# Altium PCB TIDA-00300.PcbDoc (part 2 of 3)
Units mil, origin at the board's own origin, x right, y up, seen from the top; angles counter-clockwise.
Board outline 2685 x 3089 mil, 4 copper layers (Top Layer, L2_GND-PLANE, L3_PWR-PLANE, Bottom Layer), stack 63.6 mil thick; 196 components, 87 nets, 476 pads, 171 vias.
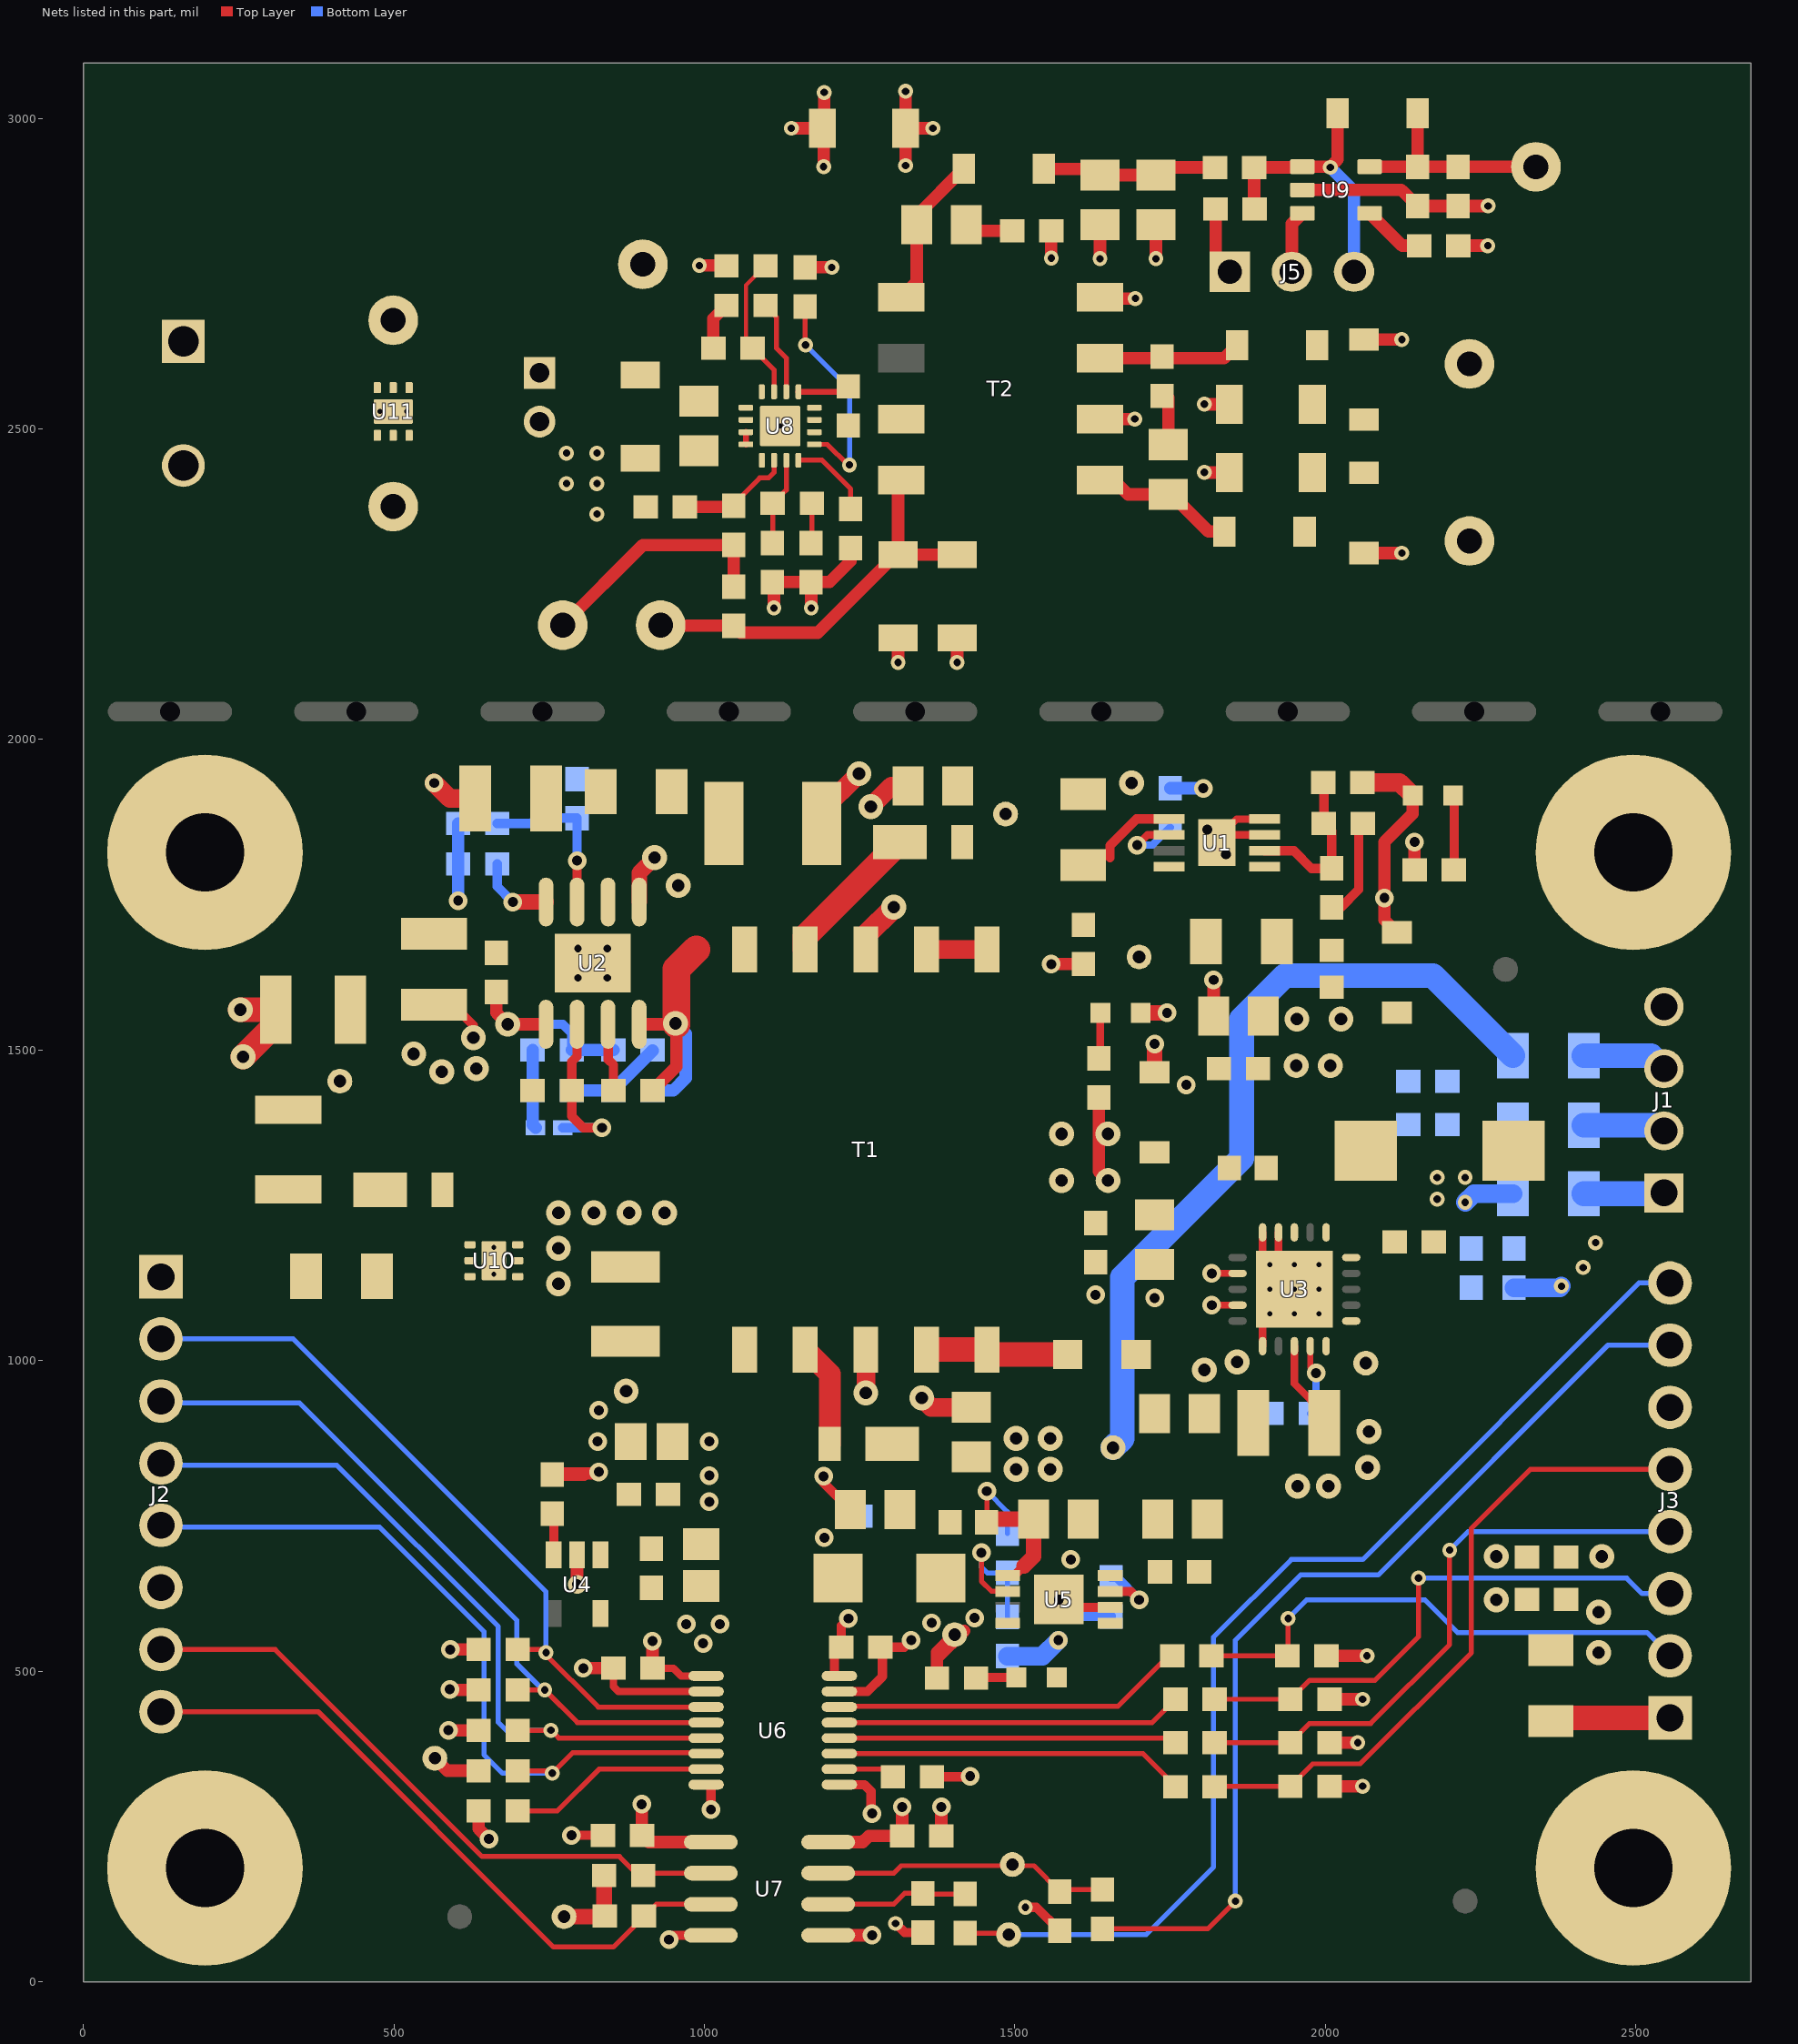
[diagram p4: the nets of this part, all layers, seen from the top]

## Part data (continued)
D1 D3 D11: "LED SmartLED Green 570NM", Alternate Manufacturer=LED, Manufacturer=OSRAM, PartNumber="LG L29K-G2J1-24-Z", Supplier Part Number 1=475-2709-2-ND
D2 D6 D9: "Diode, Schottky, 200V, 1A, PowerDI123", Manufacturer="Diodes Inc.", Supplier Part Number 1=DFLS1200DICT-ND, Value1=1A, Value2=0.85V
D4 D5: "Diode, Zener, 18V, 1W, SOD-123", Manufacturer=Panasonic, Supplier Part Number 1=DZ2W18000LCT-ND
D7: "Diode, Schottky, 60V, 1A, SOD-123F", Manufacturer="NXP Semiconductor", Supplier Part Number 1=568-4104-1-ND, Value1=1A, Value2=0.57V
D10: "DIODE ZENER 5.9V 1W PMDS", Manufacturer="Rohm Semiconductor", Supplier Part Number 1=PTZTE255.6BTR-ND, Value1=1W
D12: "Diode, Schottky, 45V, 0.1A, SOD-523", Manufacturer="Diodes Inc.", Supplier Part Number 1=SDM10U45-FDICT-ND, Value1=0.1A, Value2=0.58V
D13 D16: "Diode, Schottky, 100 V, 0.2 A, SOD-123", Manufacturer=STMicroelectronics, Supplier Part Number 1=497-5558-1-ND, Value1=0.2A, Value2=1V
D14 D15: "Diode, Zener, 16 V, 500 mW, SOD-123", Manufacturer="ON Semiconductor", Power_W=0.5, Supplier Part Number 1=MMSZ4703T1GOSCT-ND, Value1=0.5W
D17 D18: "Diode, Schottky, 30 V, 0.5 A, SOD-123", Manufacturer="Diodes Inc.", Supplier Part Number 1=B0530W-FDICT-ND, Value1=0.5A, Value2=0.43V
FID1 FID2 FID3 FID4 FID5 FID6: library part Fiducial40_0
H1 H2 H3 H4: "Machine Screw, Round, #4-40 x 1/4, Nylon, Philips panhead", Alternate Manufacturer=-, DigiKeyPartNumber=H542-ND, Manufacturer="B&F Fastener Supply"
J1: "Receptacle, 100mil, 4X1 TH", Manufacturer="TE Connectivity"
J2 J3: "Terminal Block, 8x1, 2.54 mm, TH", Manufacturer="Phoenix Contact", Supplier Part Number 1=277-1279-ND
J4: "TERMINAL BLOCK 5.08MM VERT 2POS, TH", Manufacturer="On-Shore Technology", Supplier Part Number 1=ED1609-ND
J5: "Header, 100mil, 3x1, Tin, TH", Manufacturer="TE Connectivity", Supplier Part Number 1=5-146278-3-ND
L1 L3 L4: library part MMZ1608B102C, "FERRITE CHIP 1000 OHM 300MA 0603", Manufacturer="TDK Corporation", Supplier Part Number 1=445-8672-2-ND
L2: library part IND_ELJEA_SERIES, "Inductor, Chip, ±10%", Manufacturer="EPCOS INC.", PartNumber=B82422H1332K
LBL1: library part THT-14-423-10, "Thermal Transfer Printable Labels, 0.650\" W x 0.200\" H - 10,000 per roll", Alternate Manufacturer=-, Manufacturer=Brady, Supplier Part Number 1=2065596
Logo1: library part Pb-Free
Logo2: library part FCC_disclaimer, "FCC_disclaimer"
Logo3: library part CMP-0074769-1
Logo4: library part ESD_Susceptible, "ESD Susceptible Symbol"
R1: library part CRCW04029K31FKED, "RES, 9.42k ohm, 1%, 0.063W, 0603", Manufacturer=Vishay-Dale, Power_W=0.063, Supplier Part Number 1=RNCF0603FKE9K42-ND, TempCo="100 ppm/C", Tolerance_%=1, Value1=1%, Value2=0.063W, Value_Code=9k42
R2: "RES, 110k ohm, 0.1%, 0.1W, 0603", Manufacturer="Susumu Co Ltd", Power_W=0.1, Supplier Part Number 1=RG16P110KBCT-ND, TempCo="25 ppm/C", Value1=0.1%, Value2=0.1W, Value_Code=110k
R3 R5: "RES, 4.7k ohm, 5%, 0.1W, 0603", Manufacturer=Vishay-Dale, Power_W=0.1, Supplier Part Number 1=71-CRCW0603J-4.7K-E3, TempCo="200 ppm/C", Tolerance_%=5, Value1=5%, Value2=0.1W, Value_Code=4k70
R4: "RES, 27.0k ohm, 1%, 0.1W, 0603", Manufacturer="Yageo America", Power_W=0.1, Supplier Part Number 1=311-27.0KHRCT-ND, TempCo="200 ppm/C", Tolerance_%=1, Value1=1%, Value2=0.1W, Value_Code=27k0
R6: library part RC0402JR-070RL, "RES, 0 ohm,0.1W, 1206", Manufacturer="Yageo America", Power_W=0.1, Supplier Part Number 1=311-0.0ERTR-ND, TempCo="200 ppm/C", Tolerance_%=5, Value2=0.1W, Value_Code=0000
R7 R9 R10 R11 R14 R15 R19 R20: library part RG1608P-103-B-T5, "RES, 10.0k ohm, 1%, 0.1W, 0603", Manufacturer="Vishay Dale", Power_W=0.1, Supplier Part Number 1=541-10.0KHCT-ND, TempCo="25 ppm/C", Tolerance_%=1, Value1=1%, Value2=0.1W, Value_Code=10k0
R8 R13 R16 R17 R18 R21 R25 R27 R37: library part RC0402JR-070RL, "RES, 0 ohm,5%, 0.1W, 0603", Manufacturer="Yageo America", Power_W=0.1, Supplier Part Number 1=311-0.0GRTR-ND, TempCo="200 ppm/C", Tolerance_%=5, Value1=5%, Value2=0.1W, Value_Code=0000
R12: "RES, 1.20k ohm, 0.1%, 0.1W, 0603", Manufacturer="Susumu Co Ltd", Power_W=0.1, Supplier Part Number 1=RG16P1.2KBCT-ND, TempCo="25 ppm/C", Value1=0.1%, Value2=0.1W, Value_Code=1k20
R22 R23 R24 R26: "RES, 1.50k ohm, 1%, 0.1W, 0603", Manufacturer=Vishay-Dale, Power_W=0.1, Supplier Part Number 1=541-1.50KHCT-ND, TempCo="100 ppm/C", Tolerance_%=1, Value1=1%, Value2=0.1W, Value_Code=1k50
R28: library part RT0603BRD0760K4L, "RES, 60.4k ohm, 0.1%, 0.1W, 0603", Manufacturer="Panasonic Electronic Components", Power_W=0.1, Supplier Part Number 1=P60.4KDBCT-ND, TempCo="25 ppm/C", Value1=0.1%, Value2=0.1W, Value_Code=60k4
R29: "RES, 4.87k ohm, 1%, 0.1W, 0603", Manufacturer="Yageo America", Power_W=0.1, Supplier Part Number 1=311-4.87KHRCT-ND, TempCo="200 ppm/C", Tolerance_%=1, Value1=1%, Value2=0.1W, Value_Code=4k87
R30: library part RT0603BRD07340KL, "RES, 340k ohm,1%, 0.1W, 0603", Manufacturer="Vishay Dale", Power_W=0.1, Supplier Part Number 1=541-340KHCT-ND, TempCo="25 ppm/C", Value1=1%, Value2=0.1W, Value_Code=340k
R31: library part RT0603BRD07189KL, "RES 187K OHM 1/10W .1% 0603 SMD", Manufacturer="Panasonic Electronic Components", Power_W=0.1, Supplier Part Number 1=P187KDBCT-ND, TempCo="25 ppm/C", Value1=0.1%, Value2=0.1W, Value_Code=189k
R32: library part RT0603BRD0756K2L, "RES, 56.2k ohm, 0.1%, 0.1W, 0603", Manufacturer="Panasonic Electronic Components", Power_W=0.1, Supplier Part Number 1=P56.2KDBCT-ND, TempCo="25 ppm/C", Value1=0.1%, Value2=0.1W, Value_Code=56k2
R33 R34 R35 R36: library part RC0402JR-070RL, "RES, 0 ohm,5%, 0.25W, 1206", Manufacturer="Yageo America", Power_W=0.1, Supplier Part Number 1=311-0.0ERTR-ND, TempCo="200 ppm/C", Tolerance_%=5, Value1=5%, Value2=0.125W, Value_Code=0000
R38: library part RG1608P-122-B-T5, "RES, 20K ohm, 0.1%, 0.1W, 0603", Manufacturer="Vishay Dale", Power_W=0.1, Supplier Part Number 1=TNP20.0KAACT-ND, TempCo="25 ppm/C", Value1=0.1%, Value2=0.1W, Value_Code=20K
R39: library part RG1608P-122-B-T5, "RES, 11.3K ohm, 0.1%, 0.1W, 0603", Manufacturer="panasonic electronic components", Power_W=0.1, Supplier Part Number 1=P11.3KDBCT-ND, TempCo="25 ppm/C", Value1=0.1%, Value2=0.1W, Value_Code=11K3
R40 R49: "RES, 1.0 k, 5%, 0.125 W, 0805", Manufacturer=Panasonic, Power_W=0.125, Supplier Part Number 1=P1.0KACT-ND, TempCo="200 ppm/C", Tolerance_%=5, Value1=5%, Value2=0.125W, Value_Code=1k00, ValueDisplayed=1.0k
R41 R50: "RES, 10 k, 5%, 0.1 W, 0603", Manufacturer=Vishay-Dale, Power_W=0.1, Supplier Part Number 1=541-10KGCT-ND, TempCo="200 ppm/C", Tolerance_%=5, Value1=5%, Value2=0.1W, Value_Code=10k0, ValueDisplayed=10k
R42: "RES, 220 k, 5%, 0.1 W, 0603", Manufacturer=Vishay-Dale, Power_W=0.1, Supplier Part Number 1=541-220KGCT-ND, TempCo="200 ppm/C", Tolerance_%=5, Value1=5%, Value2=0.1W, Value_Code=220k
R43: "RES, 16.2 k, 1%, 0.1 W, 0603", Manufacturer=Vishay-Dale, Power_W=0.1, Supplier Part Number 1=541-16.2KHCT-ND, TempCo="100 ppm/C", Tolerance_%=1, Value1=1%, Value2=0.1W, Value_Code=16k2, ValueDisplayed=16.2k
R44: "RES, 49.9, 1%, 0.1 W, 0603", Manufacturer=Vishay-Dale, Power_W=0.1, Supplier Part Number 1=541-49.9HCT-ND, TempCo="100 ppm/C", Tolerance_%=1, Value1=1%, Value2=0.1W, Value_Code=49R9, ValueDisplayed=49.9
R45: "RES, 75 k, 5%, 0.1 W, 0603", Manufacturer=Vishay-Dale, Power_W=0.1, Supplier Part Number 1=541-75KGCT-ND, TempCo="200 ppm/C", Tolerance_%=5, Value1=5%, Value2=0.1W, Value_Code=75k0, ValueDisplayed=75k
R46: "RES, 10.0 k, 1%, 0.1 W, 0603", Manufacturer=Vishay-Dale, Power_W=0.1, Supplier Part Number 1=541-10.0KHCT-ND, TempCo="100 ppm/C", Tolerance_%=1, Value1=1%, Value2=0.1W, Value_Code=10k0, ValueDisplayed=10.0k
R47: "RES, 0, 5%, 0.1 W, 0603", Manufacturer=Vishay-Dale, Power_W=0.1, Supplier Part Number 1=541-0.0GCT-ND, TempCo="200 ppm/C", Tolerance_%=5, Value1=5%, Value2=0.1W, Value_Code=0000, ValueDisplayed=0
R48: "RES, 240 k, 5%, 0.1 W, 0603", Manufacturer=Vishay-Dale, Power_W=0.1, Supplier Part Number 1=541-240KGCT-ND, TempCo="200 ppm/C", Tolerance_%=5, Value1=5%, Value2=0.1W, Value_Code=240k
SH-J1: "Shunt, 2.54mm, Gold, Black", Manufacturer="Wurth Elektronik", Supplier Part Number 1=732-2678-ND
T1: library part 750313995, "Transformer, 50uH, SMT", Manufacturer="Wurth Elektronik eiSos"
T2: "Transformer, 2.7 uH, SMT", Manufacturer="Wurth Elektronik", ValueDisplayed=2.7µH
TP1 TP2 TP3 TP6 TP7 TP8 TP10 TP11 TP12 TP13: library part TP-040_RND, "Test Point 40mil pad 20mil drill", Manufacturer=STD
TP4 TP5 TP9: "Test Point 40mil pad 20mil drill", Manufacturer=STD
TP14 TP15 TP17 TP20: "Test Point, Miniature, Red, TH", Color=Red, Manufacturer=Keystone, Supplier Part Number 1=36-5000-ND
TP16 TP21: "Test Point, Miniature, Black, TH", Color=Black, Manufacturer=Keystone, Supplier Part Number 1=36-5001-ND
TP18: "Test Point, Miniature, White, TH", Color=White, Manufacturer=Keystone, Supplier Part Number 1=36-5002-ND
TP19: "Test Point, Miniature, Yellow, TH", Color=Yellow, Manufacturer=Keystone, Supplier Part Number 1=36-5004-ND
U1: "-36V, -200mA, Ultralow-Noise, Negative Linear Regulator", Alternate Manufacturer=None, Manufacturer="Texas Instruments"
U2: "100V, 600mA Constant On-Time Synchronous Buck Regulator, DDA0008B", Alternate Manufacturer=None, Manufacturer="Texas Instruments"
U3: "36-V, 1-A, 4.17-µVRMS, RF LDO Voltage Regulator, RGW0020A", Alternate Manufacturer=None, Manufacturer="Texas Instruments"
U4: "IC REG LDO 3.3V 0.15A SOT23-5", Alternate Manufacturer=None, Manufacturer="Texas Instruments"
U5: library part TPS7A16XXDGN, "IC, 60-V, 6-A IQ, 100-mA, LDO Voltage Regulator with Enable and Power-Good Functions", Alternate Manufacturer=None, Manufacturer=TI
U6: library part CMP-0013040-1, "High Speed, Robust EMC Quad-Channel Digital Isolators, DBQ0016A (SSOP-16)", Alternate Manufacturer="Texas Instruments", Alternate PartNumber=ISO7741DBQ
U7: "Low-Power Bidirectional I2C Isolators, D0008A", Alternate Manufacturer=None, Manufacturer="Texas Instruments"
U8: "2.95V To 6V Input, 2W, Isolated DC/DC Converter with Integrated FETs, RTE0016F (WQFN-16)", Alternate Manufacturer="Texas Instruments"
U9: "150-mA Low-noise Low-dropout Regulator With Shutdown, DBV0005A", Alternate Manufacturer="Texas Instruments", Alternate PartNumber=LP2985-50DBVT
U10: library part CMP-0013424-7, "33-V Precision Surge Protection Clamp, DRV0006A (WSON-6)", Alternate Manufacturer="Texas Instruments", Alternate PartNumber=TVS3300DRVT
U11: library part CMP-0077837-1, "5-V Precision Surge Protection Clamp, DRV0006A (WSON-6)", Alternate Manufacturer="Texas Instruments"
ZZ1: library part AssemblyNoteLabel, Alternate Manufacturer=-
ZZ2 ZZ3 ZZ4: library part AssemblyNote, Alternate Manufacturer=-

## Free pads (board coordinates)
  oval 200x32 hole 32 slot 200 at 0 deg unplated mask+10: 0(139.44,2044.94) 0(439.44,2044.94) 0(739.44,2044.94) 0(1039.44,2044.94) 0(1339.44,2044.94) 0(1639.44,2044.94) 0(1939.44,2044.94) 0(2239.44,2044.94) 0(2539.44,2044.94)

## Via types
v1: diameter 30, hole 16, Top Layer to Bottom Layer, tented both sides, 58 vias
v2: diameter 24, hole 12, Top Layer to Bottom Layer, tented both sides, 52 vias
v3: diameter 40, hole 20, Top Layer to Bottom Layer, tented both sides, 43 vias
v4: diameter 20, hole 8, Top Layer to Bottom Layer, tented both sides, 9 vias
v5: diameter 19.68, hole 7.87, Top Layer to Bottom Layer, 5 vias
v6: diameter 25.98, hole 12, Top Layer to Bottom Layer, tented both sides, 4 vias

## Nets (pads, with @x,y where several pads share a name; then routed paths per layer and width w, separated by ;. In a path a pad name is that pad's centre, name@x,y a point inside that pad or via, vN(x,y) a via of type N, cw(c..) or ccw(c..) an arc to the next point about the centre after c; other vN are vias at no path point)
9.3V_NON_ISO: C19.1 C20.1 C26.1 C43.2 D12.2 R31.2 R37.2 T1.10 TP6.1 U4.1 | length 263.9
  Top Layer w20: R37.2@748,818.5 808,818.5 ; R37.2@755,816.5 806,816.5 808,818.5 ; v1(830,821) 827.5,818.5 808,818.5
  Bottom Layer w20: R31.2@723.5,1500 C43.2@723.5,1435 723.5,1379.84 D12.2@728.35,1375
  other v1: 828,870 830,920
+3.3V_NON_ISO: C30.1 C31.1 C35.2 C39.2 R7.2 R10.2 R11.2 R15.2 R21.1 R22.2 R23.2 TP10.1 TP12.1 U4.5 U6.1 U7.1 | length 711.4
  Top Layer w12: C35.2@916.5,505 950,505 962.5,492.5 U6.1@1010.59,492.5
  Top Layer w20: TP10.1@566,360 586,340 R15.2@636.5,340 ; v1(588,405) R10.2@636.5,405 ; v1(590,471) 591,470 R11.2@636.5,470 ; v1(591,535) R7.2@636.5,535 ; R21.1@636.5,275 636.5,246.5 v1(653,230) ; v1(899,286) 899.5,285.5 C39.2@899.5,236 910.5,225 U7.1@1010.51,225 ; C35.2@916.5,505 v1(916.5,548.5)
  Top Layer w25: TP12.1@774,105 838.5,105 R23.2@839.5,106 838.5,107 R22.2@838.5,171
  other v1: 998,545 971,576 1025,576
+5V_1: C48.1 C49.1 C50.2 J4.1 R41.2 R42.2 TP14.1 U8.1 U8.2 U8.16 U11.4 U11.5 U11.6 | length 78.2
  Top Layer w20: R42.2@1014.4,2629.67 1014.4,2677.57 R41.2@1035.5,2698.67 R41.2@1035.83,2698.34
+5V_ISO: C27.1 C36.1 C37.1 C38.2 C40.1 C45.2 D10.1 L4.2 R9.2 R12.2 R14.2 R16.2 R19.2 R20.2 R24.2 R26.2 R33.1 TP9.1 U6.16 U7.8 | length 818.2
  Top Layer w15: U6.16@1209.41,492.5 1209.41,527.91 C36.1@1220.5,539 1220.5,573.5 v1(1232,585) ; v2(1308,94) 1322.5,79.5 R24.2@1352,79.5 ; R16.2@1363.62,330 R16.2@1366.5,330 1426.98,330 v1(1427.98,331) ; v2(1517,120) 1534.5,120 R26.2@1572,82.5
  Top Layer w20: U7.8@1199.49,225 1255,225 1265,235 C40.1@1318.5,235 v1(1318.5,281.5) ; R12.2@1374.5,489 1374.5,521.5 ; TP9.1@1403,559 1374.5,530.5 1374.5,521.5 ; TP9.1@1418,565 1374.5,521.5 ; R9.2@2001.5,525 v2(2067,525) ; R20.2@2006.5,315 v2(2060,315) ; R19.2@2006.5,385 v2(2052,385) ; R14.2@2006.5,455 v2(2060,455)
  other v1: 1366,578 1435,586
  other v3: 2440,530 2440,595 2445,685
+5V_iso_1: C57.1 C58.1 D17.2 TP20.1 U9.5 | length 354.1
  Top Layer w20: U9.5@2071.13,2922.07 2148.14,2922.07 C58.1@2148.33,2921.88 ; D17.2@2148.47,3008 2148.33,3007.86 C58.1@2148.33,2921.88 ; TP20.1@2339,2921.88 C57.1@2213.33,2921.88 C58.1@2148.33,2921.88
+6V_ISO: C22.1 C29.1 C32.2 D7.1 R36.1 TP8.1 U5.5 U5.8 | length 1295.1
  Bottom Layer w40: TP8.1@1658,860 1673,875 1673,1134 1865,1326 1865,1550 1935,1620 2172.91,1620 R36.1@2301.91,1491
+15V_ISO: C17.2 C18.1 C33.2 C34.2 D5.1 L3.2 R5.1 R34.1 TP5.1 | length 222.4
  Top Layer w20: R5.1@1635,1423.5 1635,1305 TP5.1@1650,1290
  Bottom Layer w30: v2(2225,1255) 2239,1269 R34.1@2301.91,1269
  other v2: 2180,1260 2180,1295 2225,1295
  other v3: 1575,1290 1575,1365 1650,1365
+15V_iso_1: C51.1 D13.1 D14.1 TP15.1
+18V_ISO: C21.1 C23.1 D9.1 TP7.1 U3.13 U3.15 U3.16 | length 137.4
  Top Layer w12: U3.13@1950,1023.46 1950,963 1998,915 C23.1@2007.09,915
  other v3: 1955,798 2005,798 1502,825 1557,825 2068,828 1502,875 1557,875 2070,886
+24VDC_LIMIT: J2.1 R6.2
-15V_ISO: C10.2 C12.2 C24.1 C25.2 D4.2 L1.2 R3.1 R35.1 TP4.1 | length 46
  Top Layer w20: R3.1@2143.5,1790 v1(2143.5,1835)
  Top Layer w30: D4.2@2115,1560.53 D4.2@2115.96,1560.53
  other v3: 2008,1475 1954,1550 2025,1550
-15V_iso_1: C54.2 D15.2 D16.2 TP17.1
-18V_ISO: C1.2 C5.1 C7.2 D2.2 TP1.1 U1.5 U1.8 | length 132.3
  Top Layer w15: 1653,1810 1653,1829.13 1695.87,1872 U1.5@1748.4,1872
/CS0: J2.2 R7.1 U6.3 | length 1239.2
  Top Layer w8: R7.1@699.5,535 736.82,535 v2@741.82,530 ; v2(745,530) v2@741.82,530 ; U6.3@1010.59,442.5 829.32,442.5 v2@741.82,530
  Bottom Layer w8: J2.2@125,1035 338.08,1035 745,628.08 v2(745,530)
/CS0_ISO: J3.2 R8.2 R9.1 | length 847.3
  Top Layer w8: R8.2@1816.5,525 R9.1@1938.5,525 1940,526.5 v2(1940,585)
  Bottom Layer w8: v2(1940,585) 1970,615 2160,615 2212.5,562.5 2517.5,562.5 J3.2@2555,525
DGND_1: C47.2 C48.2 C49.2 C50.1 C55.2 C56.2 C59.2 C64.1 J4.2 R45.1 R46.1 R48.1 R50.1 TP16.1 TP21.1 U8.3 U8.4 U8.5 U8.17@1122,2504.67 U11.1 U11.2 U11.3 U11.7@499,2528 | length 607.2
  Top Layer w6: C64.1@1106.72,2251.05 1111.72,2256.05 C64.1@1113.1,2254.67
  Top Layer w10: U8.4@1066.88,2475.14 U8.3@1066.88,2494.83
  Top Layer w20: v2(992,2763) 1035.17,2763 R45.1@1035.5,2762.67 ; v2(1112,2211.67) C64.1@1112,2253.17 ; C64.1@1114.24,2253.53 1201.65,2253.53 1235.54,2287.43 R48.1@1235.54,2307.98 ; v2(1140,2984) 1189.74,2984 C47.2@1190.07,2983.67 C47.2@1190.4,2983.34 ; C59.2@1161.67,2760.5 C59.2@1162,2760.17 v2(1205.17,2760.17) ; v2(1172,2211.67) R50.1@1172,2253.17 ; C47.2@1190.73,2983.67 C47.2@1190.4,2983.34 ; v2(1192,2922) 1192,2981.74 C47.2@1190.4,2983.34 ; C47.2@1193,2982 v2(1193,3041.74) ; v2(1312,2124) C55.2@1312,2163.74 ; v2(1407,2124) C56.2@1407,2163.74
  other v2: 827,2363 778,2412 827,2412 778,2461 827,2461
  other v5: 1122,2504.67 477.35,2528 520.65,2528
GND: C2.1 C3.1 C4.2 C9.2 C11.1 C13.2 C19.2 C20.2 C26.2 C30.2 C31.2 C35.1 C39.1 H1.1 H3.1 J2.6 R4.1 R29.1 U2.1 U2.9 U4.2 U6.2 U6.8 U7.4 U10.1 U10.2 U10.3 U10.7@661,1161 | length 856.6
  Top Layer w12: C35.1@853.5,505 853.5,475.3 861.3,467.5 U6.2@1010.59,467.5
  Top Layer w15: C9.2@565,1572.91 595.09,1572.91 628,1540 v3(628,1520) ; v1(786,236) C39.1@836.5,236 ; v1(943,68) 950,75 U7.4@1010.51,75 ; v1(1010.59,277.41) U6.8@1010.59,317.5
  Top Layer w20: v1(795,640) U4.2@795,687.24 ; v1(805,505) C35.1@853.5,505
  Top Layer w25: U2.1@895,1738.43 895,1785 v3(920,1810)
  Top Layer w30: v1(565,1930) 590,1905 C2.1@630.91,1905
  Top Layer w40: v3(253,1565) C11.1@310,1565 310,1542 v3(257,1489)
  other v1: 1008,773 1008,815 1008,870
  other v3: 765,1124 765,1181 765,1238 822,1238 879,1238 936,1238 577,1465 633,1470 532,1494 958,1765
  other v5: 661,1139.35 661,1182.65
  other v6: 796.38,1616.38 843.62,1616.38 796.38,1663.62 843.62,1663.62
GND_ISO: C1.1 C4.1 C5.2 C7.1 C8.2 C10.1 C12.1 C15.1 C16.2 C17.1 C18.2 C21.2 C22.2 C23.2 C24.2 C25.1 C27.2 C28.2 C29.2 C32.1 C33.1 C34.1 C36.2 C37.2 C38.1 C40.2 C41.2 C44.2 C45.1 C46.2 D1.2 D3.1 D4.1 D5.2 D10.2 D11.1 H2.1 H4.1 J1.4 J3.6 R1.2 R39.1 T1.3 T1.8 TP2.1 U1.3 U1.4 U1.9 U3.4 U3.5 U3.7 U3.9 U3.11 U3.21 U5.4 U5.6 U5.9 U6.9 U6.15 U7.5 | length 2272.1
  Top Layer w11: v1(1817,1089.41) U3.9@1858.46,1089.41 ; v1(1817,1140.59) U3.7@1858.46,1140.59
  Top Layer w12: U1.9@1825,1834 U1.9@1837.4,1846.4 ; U3.11@1898.82,1023.46 U3.21@1898.82,1083.23 ; U3.21@1898.82,1166.18 U3.5@1898.82,1206.54 ; U1.3@1902,1846.4 U1.9@1837.4,1846.4 ; U1.4@1902,1872 1857,1872 1831.4,1846.4 U1.9@1837.4,1846.4 ; U3.21@1910.63,1140.59 1924.41,1140.59 U3.4@1924.41,1206.54
  Top Layer w15: v1(1192,814) 1192,803 C27.2@1235,760 ; U6.9@1209.41,317.5 1257.5,317.5 1268.32,306.68 1268.32,272.68 v1(1270,271) ; U6.15@1209.41,467.5 1262.5,467.5 1286.5,491.5 C36.2@1286.5,539 ; C36.2@1283.5,539 C36.2@1286.5,539 ; v1(1332.99,550) 1321.99,539 C36.2@1286.5,539 ; v1(1570.8,615.6) 1583.5,602.9 U5.6@1653.5,602.9
  Top Layer w20: U7.5@1199.49,75 v1(1270,75) ; C40.2@1381.5,235 v1(1381.5,281.5) ; v1(1558.5,1638.5) C7.1@1610,1638.5 ; C10.1@1820,1555 v1(1820,1613) ; D4.1@2115,1689.47 2095,1709.47 v1(2095,1745) 2095,1835 2140.52,1880.52 D1.2@2140.52,1910
  Top Layer w25: D3.1@1702.48,1560 v1(1745,1560) ; D5.2@1725,1464.47 v1(1725,1510)
  Top Layer w30: C4.1@1188.74,1865 1188.74,1884.74 v3(1249,1945) ; v3(1260,948) T1.8@1260,1017.95 ; v3(1268,1892) 1301,1925 C1.1@1328,1925 ; v3(1350,940) 1365,925 C21.2@1430,925 ; R1.2@2059.5,1931 2119.52,1931 D1.2@2140.52,1910
  Top Layer w35: T1.3@1260,1662.05 1260,1685 v3(1305,1730)
  Bottom Layer w15: v1(1570.8,615.6) 1597.9,588.5 C46.2@1655,588.5
  Bottom Layer w20: C41.2@1750,1921.5 v1(1803.5,1921.5)
  Bottom Layer w30: R39.1@1488,524.5 1544.5,524.5 v1(1570,550) ; C34.1@2304,1117.5 2377.5,1117.5 v2(2380,1120)
  other v1: 1590,680 1193,715 1725,1101 1630,1106 1776,1444 1840,1815 1810,1855
  other v2: 2415,1150 2435,1190
  other v3: 2275,615 2275,685 1805,985 1858,998 1688,1930
  other v4: 1910.63,1075.63 1950,1075.63 1989.37,1075.63 1910.63,1115 1950,1115 1989.37,1115 1910.63,1154.37 1950,1154.37 1989.37,1154.37
GND_iso_1: C47.1 C51.2 C54.1 C57.2 C58.2 C60.2 C61.1 C63.2 C65.2 C66.2 D14.2 D15.1 J5.1 T2.5 T2.7 U9.2 | length 1083.7
  Top Layer w20: v2(1323.93,2923.93) C47.1@1323.93,2983.67 ; v2(1323.93,3043.41) C47.1@1323.93,2983.67 ; v2(1368,2984) 1324.26,2984 C47.1@1323.93,2983.67 ; C65.2@1558.49,2818.67 1558.49,2775.12 v2(1558.61,2775) ; v2(1637,2774.04) C60.2@1637,2828.67 ; T2.7@1637.04,2515.65 v2@1693,2515.65 ; T2.5@1649.08,2709.67 v2@1693.98,2709.67 ; v2(1727,2774.04) C61.1@1727,2828.67 ; v2@1805,2429.67 C51.2@1843.12,2429.67 ; v2@1805,2539.67 C54.1@1843.12,2539.67 ; C63.2@1823.2,2854.14 1823.2,2775.8 J5.1@1846,2753 ; U9.2@1962.87,2884.67 2121.7,2884.67 2121.7,2884.2 2123.02,2884.2 C58.2@2148.33,2858.89 C57.2@2213.33,2858.89 v2(2261.89,2858.89) ; D14.2@2062,2300.2 v2@2122.86,2300.2 ; D15.1@2062,2644.14 2122.86,2644.14 v2(2123,2644) ; C66.2@2214,2795 v2(2261.47,2795)
  other v2: 2123,2300.06 1805,2430 1693,2516 1805,2540 1693.98,2710.02
MISO: J2.5 R15.1 U6.6 | length 1233
  Top Layer w8: R15.1@699.5,340 759,340 787.81,368.81 U6.6@1009.28,368.81
  Bottom Layer w8: J2.5@125,735 128,732 477.05,732 645,564.05 645,366 675,336 v2(755,336)
MISO_ISO: J3.5 R18.2 R20.1 | length 1061.9
  Top Layer w8: R18.2@1821.5,315 R20.1@1943.5,315 1979.5,351 2056,351 2235,530 2235,730 2330,825 J3.5@2555,825
MOSI: J2.4 R10.1 U6.5 | length 1212.6
  Top Layer w8: R10.1@699.5,405 v2(753,405) 765.5,392.5 U6.5@1010.59,392.5
  Bottom Layer w8: J2.4@125,835 128,832 408,832 668,572 668,418 681,405 v2(753,405)
MOSI_ISO: J3.4 R17.2 R19.1 | length 963.4
  Top Layer w8: R17.2@1821.5,385 R19.1@1943.5,385 1974.5,416 2073,416 2200,543 v2(2200,695)
  Bottom Layer w8: v2(2200,695) 2230,725 J3.4@2555,725
NetC2_2: C2.2 C3.2 C9.1 C11.2 L2.2 R28.2 R30.2 TP3.1 U2.2 | length 124.5
  Bottom Layer w20: v1(603.5,1740.5) R30.2@603.5,1800 R28.2@603.5,1865
NetC6_1: C6.1 C8.1 L1.1 R2.2 U1.1 | length 169.9
  Top Layer w15: C6.1@2005,1729.5 C6.1@2010,1729.5 2024.5,1729.5 2053.62,1758.62 2053.62,1858.13 R2.2@2060.5,1865
NetC6_2: C6.2 R1.1 R2.1 U1.2 | length 263.8
  Top Layer w15: U1.2@1902,1820.8 1949.2,1820.8 1977.5,1792.5 C6.2@2010,1792.5 2010,1852.5 R2.1@1997.5,1865 1997.5,1930 R1.1@1996.5,1931
NetC13_1: C13.1 D12.1 U2.6 | length 271.1
  Top Layer w15: U2.6@795,1541.57 795,1490 786.5,1481.5 C13.1@786.5,1435 786.5,1393.5 805,1375 v1(835,1375)
  Bottom Layer w15: D12.1@771.65,1375 v1(835,1375)
NetC14_1: C14.1 U2.7 | length 110.1
  Top Layer w15: U2.7@845,1541.57 845,1485 853.5,1476.5 C14.1@853.5,1435
NetC14_2: C14.2 R32.2 T1.1 U2.8 | length 472.9
  Top Layer w20: U2.8@895,1541.57 955,1541.57 955,1473.5 C14.2@916.5,1435
  Top Layer w45: v3@955,1541.57 955,1630 987.05,1662.05
  Bottom Layer w20: R32.2@916.5,1435 950,1435 970,1455 970,1526.43 v3(953.43,1543)
NetC15_2: C15.2 C16.1 L3.1 U3.1 U3.3 U3.20
NetC28_1: C28.1 L4.1 R38.2 U5.1 | length 323.5
  Top Layer w8: L4.1@1454.53,740 1455,740.47 v1(1455,790)
  Top Layer w15: U5.1@1488.5,654.2 1499.2,654.2 1514.6,669.6
  Top Layer w25: L4.1@1455,740.47 1459.53,745 C28.1@1530,745 1530,685 1514.6,669.6
  Bottom Layer w8: v1(1455,790) 1488,757 R38.2@1488,721.5
NetC41_1: C41.1 U1.6 | length 123
  Top Layer w12: v1(1697,1830) 1713.4,1846.4 U1.6@1748.4,1846.4
  Bottom Layer w12: v1(1697,1830) 1721.5,1830 C41.1@1750,1858.5
NetC42_1: C42.1 C43.1 R32.1 | length 156.1
  Bottom Layer w20: C43.1@786.5,1435 R32.1@853.5,1435 ; R32.1@853.5,1436.16 C42.1@916.5,1499.15
NetC42_2: C42.2 R4.2 R31.1 U2.5 | length 324.4
  Top Layer w20: R4.2@665,1593.5 665,1560 v3(683.43,1541.57) ; v3(683.43,1541.57) U2.5@745,1541.57
  Bottom Layer w15: v3(683.43,1541.57) 772.19,1541.57 786.5,1527.27 R31.1@786.5,1500
  Bottom Layer w20: R31.1@786.5,1500 C42.2@853.5,1500
NetC44_1: C44.1 U3.14 | length 115.9
  Top Layer w10: U3.14@1975.59,1023.46 1975.59,989.41 v1(1985,980)
  Bottom Layer w12: C44.1@1976.5,915 1985,923.5 v1(1985,980)
NetC46_1: C46.1 U5.7 | length 112.2
  Top Layer w15: U5.7@1653.5,628.5 1686.5,628.5 v1(1700,615)
  Bottom Layer w15: C46.1@1655,651.5 1663.5,651.5 v1(1700,615)
NetC52_1: C52.1 T2.2 U8.10 U8.11 U8.12
NetC52_2: C52.2 U8.13 | length 84.1
  Top Layer w10: U8.13@1151.52,2559.79 1223.29,2559.79 C52.2@1232,2568.5
NetC53_1: C53.1 R40.1 | length 72.6
  Top Layer w20: R40.1@1747,2477.66 C53.1@1747,2550.24
NetC53_2: C53.2 D16.1 T2.6 | length 229.2
  Top Layer w20: T2.6@1637.04,2613.69 1836.54,2613.69 D16.1@1857.53,2634.67
NetC55_1: C55.1 C56.1 R44.2 T2.1 TP19.1 | length 656.5
  Top Layer w20: TP19.1@929.61,2184 930.44,2183.17 R44.2@1047,2183.17 1058.17,2172 1182.63,2172 1308.23,2297.6 C55.1@1312,2297.6 ; T2.1@1316.96,2417.62 1312,2412.66 C55.1@1312,2297.6 ; C56.1@1407,2297.6 C55.1@1312,2297.6
NetC59_1: C59.1 U8.9 | length 367.6
  Top Layer w8: v2(1163,2635) 1163,2642.57 1162,2643.57 C59.1@1162,2697.17 C59.1@1170.9,2688.27 ; U8.9@1177.11,2475.14 1197.94,2475.14 1231.09,2442 v2(1233.61,2442)
  Bottom Layer w8: v2(1163,2635) 1233.61,2564.39 v2(1233.61,2442)
NetC60_1: C60.1 C61.2 D18.1 R47.1 | length 287.2
  Top Layer w20: D18.1@1544.36,2918.67 1627,2918.67 C60.1@1637,2908.67 C61.2@1727,2908.67 1739.33,2921 R47.1@1822.26,2921
NetC62_1: C62.1 C64.2 U8.7 | length 142.3
  Top Layer w8: C64.2@1109.61,2316.5 1110.11,2317 C62.1@1110.11,2380 1131.84,2401.73 U8.7@1131.84,2449.55
NetC62_2: C62.2 R50.2 | length 66.4
  Top Layer w6: R50.2@1174.24,2316.52 R50.2@1175.74,2318.02
  Top Layer w8: R50.2@1172,2316.17 1173.11,2317.27 C62.2@1173.11,2380
NetC63_1: C63.1 D17.1 J5.3 R47.2 U9.1 | length 464.9
  Top Layer w20: C63.1@1886.19,2854.14 1885.25,2855.07 R47.2@1885.25,2921 1961.8,2921 U9.1@1962.87,2922.07 2008,2922.07 2019.53,2933.6 D17.1@2019.53,3008
  Bottom Layer w20: v2(2008,2921) 2046,2883 J5.3@2046,2753
NetC65_1: C65.1 R49.1 | length 77.6
  Top Layer w20: R49.1@1422,2828.67 1432,2818.67 C65.1@1495.5,2818.67
NetC66_1: C66.1 U9.4 | length 101.5
  Top Layer w20: U9.4@2071.13,2847.27 2123.4,2795 C66.1@2151.01,2795
NetD1_1: D1.1 R3.2 | length 119
  Top Layer w15: R3.2@2207.48,1790.98 D1.1@2207.48,1910
NetD2_1: D2.1 T1.2 | length 214.9
  Top Layer w40: T1.2@1162.36,1662.05 1162.36,1682.56 D2.1@1299.8,1820
NetD3_2: D3.2 R5.2 | length 74.5
  Top Layer w12: R5.2@1635,1486.5 1637.52,1489.02 D3.2@1637.52,1560
NetD6_1: D6.1 L2.1
NetD6_2: D6.2 R6.1 U10.4 U10.5 U10.6
NetD7_2: D7.2 T1.6 T1.7 | length 230.5
  Top Layer w40: T1.7@1357.64,1017.95 T1.6@1455.28,1017.95 1463.23,1010 D7.2@1584.88,1010
NetD9_2: D9.2 T1.9 | length 168.3
  Top Layer w35: T1.9@1162.36,1017.95 1201.8,978.51 1201.8,941 D9.2@1201.8,866
NetD11_2: D11.2 R12.1 | length 65.4
  Top Layer w15: R12.1@1437.5,489 1438.5,490 D11.2@1502.52,490
NetD13_2: D13.2 R40.2 T2.8 | length 234.9
  Top Layer w20: T2.8@1637.04,2417.62 1659.04,2417.62 1682,2394.67 R40.2@1747,2394.67 1752,2394.67 1812,2334.67 D13.2@1837.53,2334.67
NetD18_2: D18.2 R49.2 T2.4 | length 248.6
  Top Layer w20: T2.4@1316.96,2711.72 1342,2736.76 R49.2@1342,2828.67 1342,2843.14 D18.2@1417.53,2918.67
NetJ1_1: J1.1 R34.2 | length 148.4
  Top Layer w30: J1.1@2531.5,1283.5 J1.1@2545,1270
  Bottom Layer w40: R34.2@2416.09,1269 2544,1269 J1.1@2545,1270
NetJ1_2: J1.2 R35.2 | length 132.6
  Bottom Layer w40: R35.2@2416.09,1379 2536,1379 J1.2@2545,1370
NetJ1_3: J1.3 R36.2 | length 137.6
  Bottom Layer w40: R36.2@2416.09,1491 2524,1491 J1.3@2545,1470
NetJ3_1: J3.1 R33.2 | length 194.1
  Top Layer w40: R33.2@2363,419.91 2368.09,425 J3.1@2555,425
NetJ5_2: J5.2 U9.3 | length 101.3
  Top Layer w20: J5.2@1946,2753 1946,2830.4 U9.3@1962.87,2847.27
NetR8_1: R8.1 U6.14 | length 578.3
  Top Layer w8: U6.14@1209.41,442.5 1210.72,443.81 1666.18,443.81 1747.37,525 R8.1@1753.5,525
NetR13_1: R13.1 U6.13 | length 564.6
  Top Layer w8: U6.13@1209.41,417.5 1721,417.5 R13.1@1758.5,455
NetR16_1: R16.1 U6.10 | length 99.3
  Top Layer w8: U6.10@1209.41,342.5 1291,342.5 R16.1@1303.5,330
NetR17_1: R17.1 U6.12 | length 555.7
  Top Layer w8: U6.12@1211.91,395 1209.41,392.5 1751,392.5 R17.1@1758.5,385
NetR18_1: R18.1 U6.11 | length 570.8
  Top Layer w8: U6.11@1209.41,367.5 1706,367.5 R18.1@1758.5,315
NetR21_2: R21.2 U6.7 | length 339.1
  Top Layer w8: R21.2@699.5,275 763,275 830.5,342.5 U6.7@1010.59,342.5
NetR24_1: R24.1 R25.1 U7.6 | length 228.2
  Top Layer w8: U7.6@1199.49,125 1304.8,125 1322.3,142.5 R24.1@1352,142.5 1353,141.5 R25.1@1420,141.5
NetR26_1: R26.1 R27.1 TP11.1 U7.7 | length 464.9
  Top Layer w8: U7.7@1199.49,175 1305,175 1317,187 1530.5,187 R26.1@1572,145.5 1575,148.5 R27.1@1641,148.5
NetR28_1: R28.1 R29.2 U2.3 | length 267.1
  Top Layer w15: U2.3@795,1738.43 v1(795,1805)
  Bottom Layer w15: R28.1@666.5,1865 721.5,1865 730,1873.5 R29.2@795,1873.5 v1(795,1805)
NetR30_1: R30.1 U2.4 | length 125.4
  Top Layer w25: v1(691.57,1738.43) U2.4@745,1738.43
  Bottom Layer w15: R30.1@666.5,1800 666.5,1763.5 v1(691.57,1738.43)
NetR37_1: R37.1 U4.3 | length 72.2
  Top Layer w15: R37.1@748,755.5 757.6,745.91 U4.3@757.6,687.24
NetR38_1: R38.1 R39.2 U5.2 | length 235.2
  Top Layer w8: v1(1446,691) 1446,645 1462.4,628.6 U5.2@1488.5,628.6
  Bottom Layer w8: v1(1446,691) 1446,668 1455.5,658.5 R38.1@1488,658.5 R39.2@1488,587.5
NetR41_1: R41.1 U8.14 | length 153.1
  Top Layer w8: R41.1@1097.39,2698.67 1115.9,2680.17 1115.9,2630.1 1131.84,2614.16 U8.14@1131.84,2559.79
NetR42_1: R42.1 R45.2 U8.15 | length 234.6
  Top Layer w6: R42.1@1077.39,2629.67 1067,2640.07 1067,2731.17 R45.2@1098.49,2762.67
  Top Layer w8: R42.1@1077.39,2629.67 1112.15,2594.91 U8.15@1112.15,2559.79
NetR43_1: R43.1 R44.1 TP18.1 | length 395.5
  Top Layer w20: TP18.1@772,2184 901.17,2313.17 R43.1@1047,2313.17 R44.1@1047,2246.17
NetR43_2: R43.2 R46.2 U8.6 | length 171.2
  Top Layer w8: R43.2@1045.9,2377.66 1089.24,2421 1103.33,2421 1112.15,2429.83 U8.6@1112.15,2449.55
  Top Layer w20: R46.2@983.49,2374.67 1042.91,2374.67 R43.2@1045.9,2377.66
NetR48_2: R48.2 U8.8 | length 135.5
  Top Layer w8: U8.8@1151.52,2449.55 1189.32,2449.55 1235.54,2403.33 R48.2@1235.54,2370.97
NetT1_4: T1.4 T1.5 | length 97.6
  Top Layer w30: T1.4@1357.64,1662.05 T1.5@1455.28,1662.05
SCL: J2.8 R23.1 U7.3 | length 1071.1
  Top Layer w8: J2.8@125,435 378,435 757,56 853.5,56 922.5,125 U7.3@1010.51,125
SCL_ISO: J3.8 R25.2 TP13.1 | length 1787.3
  Top Layer w8: R25.2@1420,78.5 1487.5,78.5 TP13.1@1490,76
  Bottom Layer w8: TP13.1@1490,76 1711,76 1820,185 1820,555 1945,680 2060,680 2505,1125 J3.8@2555,1125
SCLK: J2.3 R11.1 U6.4 | length 1184.6
  Top Layer w8: R11.1@699.5,470 v2(743,470) 795.5,417.5 U6.4@1010.59,417.5
  Bottom Layer w8: J2.3@125,935 128,932 348,932 698,582 698,511.73 739.73,470 v2(743,470)
SCLK_ISO: J3.3 R13.2 R14.1 | length 879.9
  Top Layer w8: R13.2@1821.5,455 R14.1@1943.5,455 1944.11,455 1974.81,485.7 2080,485.7 2150,555.7 v2(2150,650)
  Bottom Layer w8: v2(2150,650) 2485,650 2510,625 J3.3@2555,625
SDA: J2.7 R22.1 U7.2 | length 1043.5
  Top Layer w8: J2.7@125,535 309,535 642.3,201.7 863.16,201.7 893.86,171 R22.1@901.5,171 ; R22.1@899.63,162 912.63,175 U7.2@1010.51,175
SDA_ISO: J3.7 R27.2 | length 1549.2
  Top Layer w8: R27.2@1641,85.5 1810.5,85.5 v2(1855,130)
  Bottom Layer w8: v2(1855,130) 1855,550 1960,655 2085,655 2455,1025 J3.7@2555,1025
pads on no net: FID1.1 FID2.1 FID3.1 FID4.1 FID5.1 FID6.1 SH-J1.0 T2.3 U1.7 U3.2 U3.6 U3.8 U3.10 U3.12 U3.17 U3.18 U3.19 U4.4 U5.3 U8.17@1122,2504.67 U10.7@661,1143.28 U10.7@661,1178.72 U11.7@481.28,2528 U11.7@516.72,2528

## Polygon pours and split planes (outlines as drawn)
NetD6_2 on Top Layer "vdd" (solid, remove dead copper, pour order 153): 561,1158 553,1150 515,1150 512,1153 512,1175.25 505.25,1182 446,1182 440,1176 440,1097 446,1091 627,1091 633,1097 633,1306 626,1313 565,1313 561,1309
+5V_iso_1 on Top Layer "vdd" (solid, remove dead copper, pour order 125): 2109,2943 2119,2953 2119,3027 2130,3038 2196,3038 2203,3031 2203,2989 2211,2981 2391.48,2981 2399.48,2973 2399.48,2875.48 2392,2868 2311,2868 2282,2897 2057,2897 2049,2905 2049,2938 2054,2943
DGND_1 on Top Layer "vdd" (solid, remove dead copper, pour order 123): 130,2539 110,2519 110,2314 123.8,2300.2 786.53,2300.2 825.33,2339 923,2339 931,2347 931,2414 939,2422 1087.91,2422 1098.49,2432.58 1098.49,2460.81 1106.72,2469.04 1153.04,2469.04 1157,2473 1157,2534 1152,2539 1090,2539 1088,2537 1088,2499 1034,2499 1028,2493 815.02,2493 769.02,2539
NetC52_1 on Top Layer "NETC52_1_L01_P117" (solid, remove dead copper, pour order 117): 1165.88,2539.67 1192,2539.67 1197,2534.67 1352,2534.67 1352,2484 1165.73,2484
-15V_iso_1 on Top Layer "-15V_ISO_1_L01_P115" (solid, pour order 115): 2152,2494.67 2263.67,2494.67 2276,2507 2276,2640 2264,2652 2197,2652 2185,2640 2185,2580.5 2159.17,2554.67 2007,2554.67 2007,2665.61 1997.94,2674.67 1959.28,2674.67 1952,2667.39 1952,2502.61 1959.94,2494.67
+15V_iso_1 on Top Layer "+15V_ISO_1_L01_P113" (solid, pour order 113): 2265.56,2454.67 2276.23,2444 2276.23,2289.34 2261.89,2275 2201,2275 2188,2288 2188,2354.98 2173.31,2369.67 1987,2369.67 1987,2309.67 1982,2304.67 1945.94,2304.67 1942,2308.61 1942,2359.67 1942,2459.58 1947.09,2464.67 2001.61,2464.67 2011.61,2454.67
+5V_1 on Top Layer "+5V_1_L01_P107" (solid, pour order 107): 119,2562 105,2576 105,2715 129,2739 821.57,2739 894.57,2666 1031.9,2666 1045.9,2652 1045.9,2589.67 1050.9,2584.67 1080.9,2584.67 1095.9,2569.67 1095.9,2549.67 1080.9,2549.67 1075.9,2544.67 1075.9,2514.67 1070.9,2509.67 1050.9,2509.67 1040.9,2519.67 868.33,2519.67 827,2561 738,2561 737,2562
GND_ISO on Top Layer "Top Layer-No Net 1" (hatched 90Degree grid 5 track 10, remove dead copper, pour order 68): 1190,630 1185,635 1185,760 1202,790 1259,790 1259,724 1244,724 1240,720 1240,635 1235,630
+18V_ISO on Top Layer "Top Layer-No Net 1" (hatched 90Degree grid 5 track 10, remove dead copper, pour order 54): 1477,884 1510,915 1570,915 1580,905 1580,805 1575,800 1288,802 1261,825 1261,871 1272,885
GND_ISO on Top Layer "Bottom Layer-No Net" (solid, remove dead copper, pour order 42): 2159,1147 2160,1242 2164.45,1247.45 2224.45,1247.45 2253,1276 2253,1398 2277,1422 2425.95,1422 2451,1396.95 2451,1153 2401,1103 2203,1103
-15V_ISO on Top Layer "Top Layer-No Net 1" (hatched 90Degree grid 5 track 10, remove dead copper, pour order 61): 2135,1605 2135,1535 2130,1530 2073,1530 2057,1516 2056,1442 2036,1428.55 2010,1430 1890,1430 1875,1445 1875,1600 1885,1610 2130,1610
NetC15_2 on Top Layer "Top Layer-No Net 1" (hatched 90Degree grid 5 track 10, remove dead copper, pour order 57): 2035,1160 2095,1160 2126,1175 2126,1210 2106,1231 2105,1396 1937,1396 1895,1376 1895,1275 1900,1270 1930,1270 1945,1255 1945,1200 1955,1200 1955,1230 1960,1235 1990,1235 1995,1230 1995,1200 2025,1200 2035,1190
+18V_ISO on Top Layer "Top Layer-No Net 1" (hatched 90Degree grid 5 track 10, remove dead copper, pour order 56): 2020,780 2101,781 2127,826 2127,879 2090,930 2090,1060 2080,1070 2035,1070 2035,1050 2020,1035 2000,1035 2000,980 1985,965 1945,965 1935,955 1935,870 1920,855 1920,790 1930,780
NetD6_1 on Top Layer "Bottom Layer-No Net" (solid, remove dead copper, pour order 47): 517,1305 525,1297 525,1240 514,1230 270,1230 260,1240 260,1296.65 268.35,1305
GND on Top Layer "Top Layer-No Net 7" (hatched 90Degree grid 5 track 8, remove dead copper, pour order 71): 645,1670 645,1640 650,1635 690,1635 730,1595 895,1595 905,1605 905,1665 1000,1755 1030,1780 1059,1782 1058,1869 1058,1962 1055,1965 900,1965 890,1955 890,1695 875,1680 655,1680
NetC14_2 on Top Layer "Top Layer-No Net" (hatched 90Degree grid 5 track 8, remove dead copper, pour order 72): 980,1400 975,1395 910,1395 905,1400 905,1480 890,1495 890,1555 895,1560 920,1560 930,1570 930,1660 970,1700 1065,1700 1070,1695 1070,1625 980,1625
NetC6_1 on Top Layer "Top Layer-No Net 1" (hatched 90Degree grid 5 track 10, remove dead copper, pour order 59): 1894.17,1800 1935,1800 1940,1795 1940,1770 1965,1745 2025,1745 2035,1735 2035,1650 1890,1650 1890,1795
GND_ISO on Top Layer "Top Layer-No Net 1" (hatched 90Degree grid 5 track 10, remove dead copper, pour order 62): 1585,1170 1765,1170 1770,1165 1770,1095 1765,1090 1585,1090 1575,1100 1575,1160
GND on Top Layer "Top Layer-No Net" (hatched 90Degree grid 5 track 8, remove dead copper, pour order 69): 1030,680 930,680 930,893.1 946.9,910 1025,910 1040,895 1040,690
+3.3V_NON_ISO on Top Layer "Top Layer-No Net" (hatched 90Degree grid 5 track 8, remove dead copper, pour order 70): 855,610 895,650 1025,650 1035,640 1035,540 1030,535 970,535 960,545 960,580 950,590 885,590 870,575 815,575 810,580 810,605 815,610
+15V_ISO on Top Layer "Top Layer-No Net 1" (hatched 90Degree grid 5 track 10, remove dead copper, pour order 60): 1855,1360 1855,1265 1805,1215 1570,1215 1550,1235 1550,1360 1570,1380 1835,1380
GND_ISO on Top Layer "Top Layer-No Net 1" (hatched 90Degree grid 5 track 10, remove dead copper, pour order 53): 1790,645 1860,645 1870,655 1870,830 1915,875 1915,970 1875,1010 1800,1010 1790,1000
-18V_ISO on Top Layer "Top Layer-No Net 1" (hatched 90Degree grid 5 track 10, remove dead copper, pour order 66): 1560,1685 1680,1685 1765,1770 1765,1797 1672,1797 1665,1804 1665,1840 1690,1865 1690,1877 1682,1877 1630,1825 1530,1825 1505,1850 1505,1940 1490,1955 1365,1955 1350,1940 1350,1880 1385,1845 1385,1765 1415,1735 1510,1735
